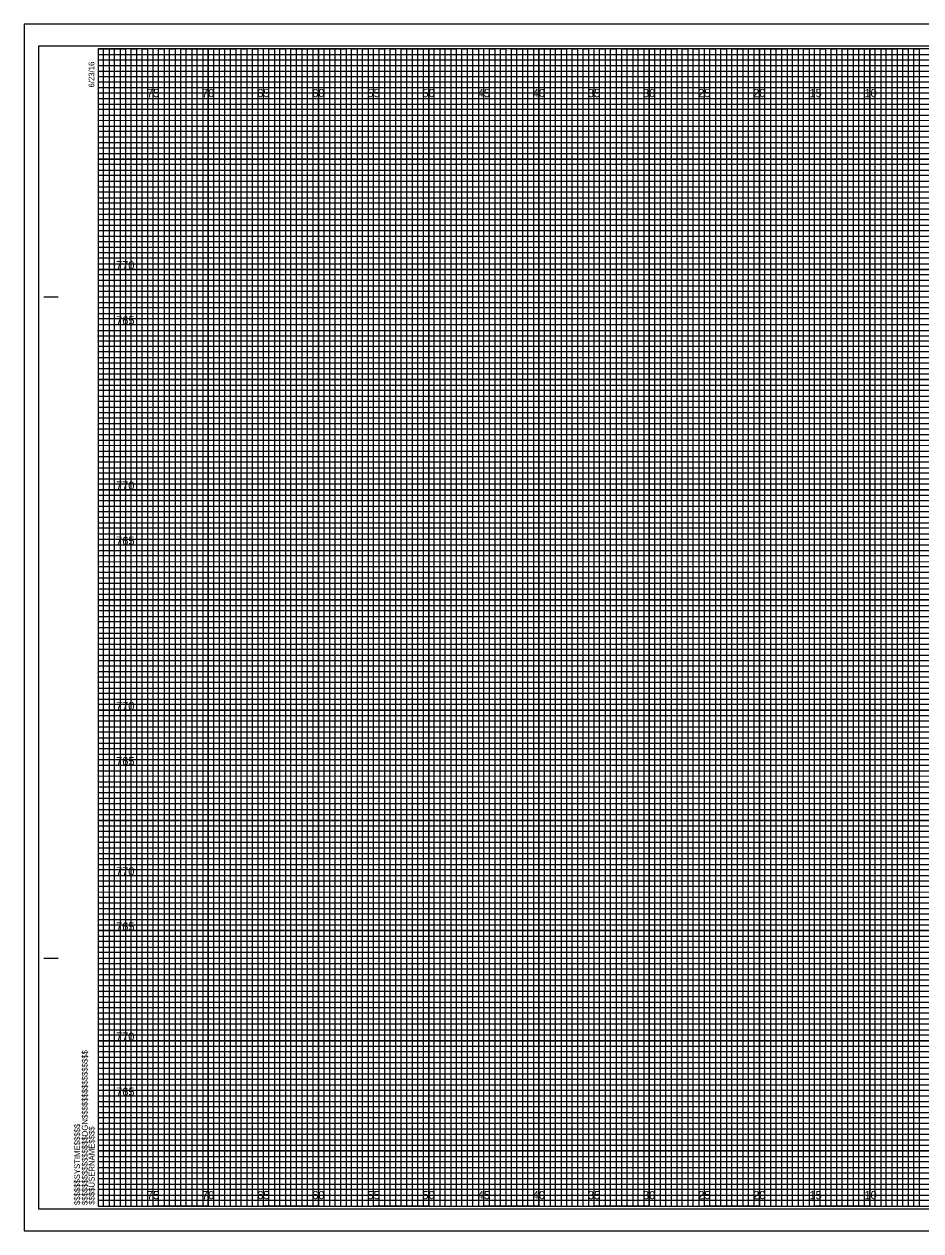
# Model space of a CAD drawing. Extents: x -7 to 162, y -2 to 107.
# Drawn here: x -6.7 to 74.6, y -2.3 to 107.3 of the extents above; entities that cross this region are included whole.
import ezdxf

# ---------------------------------------------------------------- set-up
doc = ezdxf.new("R2010")
doc.units = 0
for name, color, linetype in [('Exist XS Center Line Elevation Label', 7, 'Continuous'), ('Exist XS Ground Line', 7, 'Continuous'), ('Old_Level_63', 7, 'Continuous'), ('Prop CMT Pvmt Course 1', 7, 'Continuous'), ('Prop CMT Pvmt Course 1 CG', 7, 'Continuous'), ('Prop XS Elevation Labels', 7, 'Continuous'), ('Prop XSC Text', 7, 'Continuous'), ('Sheet Cross Section Grid Major CELL', 7, 'Continuous'), ('Sheet Cross Section Grid Minor 2 CELL', 7, 'Continuous'), ('Sheet Cutting Line CELL', 7, 'Continuous'), ('Sheet DOT Grid CELL', 7, 'Continuous')]:
    doc.layers.add(name, color=color, linetype=linetype)

msp = doc.modelspace()

# ---------------------------------------------------------------- linework, layer by layer
at = {"layer": 'Exist XS Center Line Elevation Label'}
msp.add_lwpolyline([(-5.4, -0.25), (161.2, -0.25), (161.2, 105.25), (-5.4, 105.25)], close=True, dxfattribs=at)
at = {"layer": 'Exist XS Ground Line'}
msp.add_lwpolyline([(-6.7, -2.25), (161.65, -2.25), (161.65, 107.25), (-6.7, 107.25)], close=True, dxfattribs=at)
at = {"layer": 'Old_Level_63'}
for p, q in [((-4.9, 82.5), (-3.65, 82.5)), ((-4.85, 82.5), (-3.6, 82.5)), ((-4.9, 22.5), (-3.65, 22.5)), ((-4.85, 22.5), (-3.6, 22.5)), ((0, 0), (0, 0)), ((0, 0), (0, 0)), ((0, 0), (0, 0)), ((0, 0), (0, 0)), ((0, 0), (0, 0)), ((0, 0), (0, 0)), ((0, 0), (0, 0))]:
    msp.add_line(p, q, dxfattribs=at)
msp.add_lwpolyline([(160, 105), (0, 105), (0, 0), (160, 0)], close=True, dxfattribs=at)
at = {"layer": 'Prop CMT Pvmt Course 1'}
for points in [[(0, 105), (2.5, 105), (2.5, 0), (7.5, 0), (7.5, 105), (12.5, 105), (12.5, 0), (17.5, 0), (17.5, 105), (22.5, 105), (22.5, 0), (27.5, 0), (27.5, 105), (32.5, 105), (32.5, 0), (37.5, 0), (37.5, 105), (42.5, 105), (42.5, 0), (47.5, 0), (47.5, 105), (52.5, 105), (52.5, 0), (57.5, 0), (57.5, 105), (62.5, 105), (62.5, 0), (67.5, 0), (67.5, 105), (72.5, 105), (72.5, 0), (77.5, 0)], [(0, 102.5), (137.5, 102.5)], [(0, 92.5), (160, 92.5), (160, 97.5), (0, 97.5)], [(0, 82.5), (160, 82.5), (160, 87.5), (0, 87.5)], [(0, 72.5), (160, 72.5), (160, 77.5), (0, 77.5)], [(0, 62.5), (160, 62.5), (160, 67.5), (0, 67.5)], [(0, 52.5), (160, 52.5), (160, 57.5), (0, 57.5)], [(0, 42.5), (160, 42.5), (160, 47.5), (0, 47.5)], [(0, 32.5), (160, 32.5), (160, 37.5), (0, 37.5)], [(0, 22.5), (160, 22.5), (160, 27.5), (0, 27.5)], [(0, 12.5), (160, 12.5), (160, 17.5), (0, 17.5)], [(0, 2.5), (160, 2.5), (160, 7.5), (0, 7.5)]]:
    msp.add_lwpolyline(points, dxfattribs=at)
at = {"layer": 'Prop XSC Text'}
for p, q in [((0, 104.5), (130, 104.5)), ((130, 103.99), (0, 103.99)), ((0, 103.99), (0, 103.5)), ((0, 103.5), (130, 103.5)), ((130, 102.95), (0, 102.95)), ((0, 102.95), (0, 102)), ((0, 102), (160, 102))]:
    msp.add_line(p, q, dxfattribs=at)
for points in [[(0, 101.5), (135, 101.5), (160, 101.5), (160, 101), (0, 101)], [(0, 100.5), (160, 100.5), (160, 99.5), (0, 99.5)], [(0, 99), (160, 99), (160, 98.5), (0, 98.49)], [(0, 98), (160, 98), (160, 97), (0, 97)], [(0, 96.5), (160, 96.5), (160, 96), (0, 96)], [(0, 95.5), (160, 95.5), (160, 94.5), (0, 94.5)], [(0, 94), (160, 94), (160, 93.5), (0, 93.5)], [(0, 93), (160, 93), (160, 92), (0, 92)], [(0, 91.5), (160, 91.5), (160, 91), (0, 91)], [(0, 90.5), (160, 90.5), (160, 89.5), (0, 89.5)], [(0, 89), (160, 89), (160, 88.5), (0, 88.5)], [(0, 88), (160, 88), (160, 86.98), (160, 86.5), (160, 86), (0, 86)], [(0, 87), (160, 87), (160, 86.5), (0, 86.5)], [(0, 85.5), (160, 85.5), (160, 84.5), (0, 84.52)], [(0, 84.52), (160, 84.5), (160, 84), (0, 84)], [(0, 83.5), (160, 83.5), (160, 83), (0, 83)], [(0, 82), (160, 82), (160, 81.5), (0, 81.5)], [(0, 81), (160, 81), (160, 80.5), (0, 80.5)], [(-0.04, 79.45), (160, 79.45), (160, 78.94), (-0.04, 78.94)], [(0, 78.5), (160, 78.5), (160, 78), (0, 78)], [(0, 77), (160, 77), (160, 76.5), (0, 76.5)], [(0, 76), (160, 76), (160, 75.5), (0, 75.5)], [(0, 74.5), (160, 74.5), (160, 74), (0, 74)], [(0, 73.5), (160, 73.5), (160, 73), (0, 73)], [(0, 72), (160, 72), (160, 71.5), (0, 71.5)], [(0, 71), (160, 71), (160, 70.5), (0, 70.5)], [(0, 69.5), (160, 69.5), (160, 68.99), (0, 69)], [(0, 68.5), (160, 68.5), (160, 68), (0, 68)], [(0, 67), (160, 67), (160, 66.5), (0, 66.5)], [(0, 66), (160, 66), (160, 65.5), (0, 65.5)], [(0, 64.5), (160, 64.5), (160, 64), (0, 64)], [(0, 63.5), (160, 63.5), (160, 63), (0, 63)], [(0, 62), (160, 62), (160, 61.5), (0, 61.5)], [(0, 61), (160, 61), (160, 60.5), (0, 60.5)], [(0, 59.5), (160, 59.5), (160, 59), (0, 59)], [(0, 58.5), (160.03, 58.45), (160, 58), (0, 58)], [(0, 57), (160, 57), (160, 56.5), (0, 56.5)], [(0, 56), (160, 56), (160, 55.5), (0, 55.5)], [(0, 54.5), (160, 54.5), (160, 54), (0, 54)], [(0, 53.5), (160, 53.5), (160, 53), (0, 53)], [(0, 52), (160, 52), (160, 51.5), (0, 51.5)], [(0, 51), (160, 51), (160, 50.5), (0, 50.5)], [(0, 49.5), (160, 49.5), (160, 49), (0, 49)], [(0, 48.5), (160, 48.5), (160, 48), (0, 48)], [(0, 47), (160, 47), (160, 46.5), (0, 46.5)], [(0, 46), (160, 46), (160, 45.5), (0, 45.5)], [(0, 44.5), (160, 44.5), (160, 44), (0, 44)], [(0, 43.5), (160, 43.5), (160, 43), (0, 43)], [(0, 42), (160, 42), (160, 41.5), (0, 41.5)], [(0, 41), (160, 41), (160, 40.5), (0, 40.5)], [(0, 39.5), (160, 39.5), (160, 38.99), (0, 39)], [(0, 38.5), (160, 38.5), (160, 38), (0, 38)], [(0, 37), (160, 37), (160, 36.5), (0, 36.5)], [(0, 36), (160, 36), (160, 35.5), (0, 35.5)], [(0, 34.5), (160, 34.5), (160, 34), (0, 34)], [(0, 33.5), (160, 33.5), (160, 33), (0, 33)], [(0, 32), (160, 32), (160, 31.5), (0, 31.5)], [(0, 31), (160, 31), (160, 30.5), (0, 30.5)], [(0, 29.5), (160, 29.5), (160, 29), (0, 29)], [(0, 28.5), (160.03, 28.46), (160, 28), (0, 28)], [(0, 27), (160, 27), (160, 26.5), (0, 26.5)], [(0, 26), (160, 26), (160, 25.5), (0, 25.5)], [(0, 24.5), (160, 24.5), (160, 24), (0, 24)], [(0, 23.5), (160, 23.5), (160, 23), (0, 23)], [(0, 22), (160, 22), (160, 21.5), (0, 21.5)], [(0, 21), (160, 21), (160, 20.5), (0, 20.5)], [(0, 19.5), (160, 19.5), (160, 19), (0, 19)], [(0, 18.5), (160, 18.5), (160, 18), (0, 18)], [(0, 17), (160, 17), (160, 16.5), (0, 16.5)], [(0, 16), (160, 16), (160, 15.5), (0, 15.5)], [(0, 14.5), (160, 14.5), (160, 14), (0, 14)], [(0, 13.5), (160, 13.5), (160, 13), (0, 13)], [(0, 12), (160, 12), (160, 11.5), (0, 11.5)], [(0, 11), (160, 11), (160, 10.5), (0, 10.5)], [(0, 9.5), (160, 9.5), (160, 9), (0, 9)], [(0, 8.5), (160, 8.5), (160, 8), (0, 8)], [(0, 7), (160, 7), (160, 6.5), (0, 6.5)], [(0, 6), (160, 6), (160, 5.5), (0, 5.5)], [(0, 4.5), (160, 4.5), (160, 4), (0, 4)], [(0, 3.5), (160, 3.5), (160, 3), (0, 3)], [(0, 2), (160, 2), (160, 1.5), (0, 1.5)], [(0, 1), (160, 1), (160, 0.5), (0, 0.5)]]:
    msp.add_lwpolyline(points, dxfattribs=at)
at = {"layer": 'Sheet Cross Section Grid Major CELL'}
for p, q in [((5, 105), (0, 105)), ((5, 0), (5, 105)), ((15, 105), (10, 105)), ((10, 105), (10, 0)), ((15, 0), (15, 105)), ((25, 105), (20, 105)), ((20, 105), (20, 0)), ((25, 0), (25, 105)), ((35, 105), (30, 105)), ((30, 105), (30, 0)), ((35, 0), (35, 105)), ((45, 105), (40, 105)), ((40, 105), (40, 0)), ((45, 0), (45, 105)), ((55, 105), (50, 105)), ((50, 105), (50, 0)), ((55, 0), (55, 105)), ((65, 105), (60, 105)), ((60, 105), (60, 0)), ((65, 0), (65, 105)), ((75, 105), (70, 105)), ((70, 105), (70, 0)), ((10, 0), (5, 0)), ((20, 0), (15, 0)), ((30, 0), (25, 0)), ((40, 0), (35, 0)), ((50, 0), (45, 0)), ((60, 0), (55, 0)), ((70, 0), (65, 0))]:
    msp.add_line(p, q, dxfattribs=at)
for points in [[(0, 100), (160, 100), (160, 95), (0, 95)], [(0, 90), (160, 90), (160, 85), (0, 85)], [(0, 80), (160, 80), (160, 75), (0, 75)], [(0, 70), (160, 70), (160, 65), (0, 65)], [(0, 60), (160, 60), (160, 55), (0, 55)], [(0, 50), (160, 50), (160, 45), (0, 45)], [(0, 40), (160, 40), (160, 35), (0, 35)], [(0, 30), (160, 30), (160, 25), (0, 25)], [(0, 20), (160, 20), (160, 15), (0, 15)], [(0, 10), (160, 10), (160, 5), (0, 5)]]:
    msp.add_lwpolyline(points, dxfattribs=at)
at = {"layer": 'Sheet Cross Section Grid Minor 2 CELL'}
for points in [[(0, 0), (0.5, 0), (0.5, 105), (1, 105), (1, 0)], [(1, 0), (1.5, 0), (1.5, 105), (2, 105), (2, 0)], [(2.5, 0), (3, 0), (3, 105), (3.5, 105), (3.5, 0)], [(3.5, 0), (4, 0), (4, 105), (4.5, 105), (4.5, 0)], [(5, 0), (5.5, 0), (5.5, 105), (6, 105), (6, 0)], [(6, 0), (6.5, 0), (6.5, 105), (7, 105), (7, 0)], [(7.5, 0), (8, 0), (8, 105), (8.5, 105), (8.5, 0)], [(8.5, 0), (9, 0), (9, 105), (9.5, 105), (9.5, 0)], [(10, 0), (10.5, 0), (10.5, 105), (11, 105), (11, 0)], [(11, 0), (11.5, 0), (11.5, 105), (12, 105), (12, 0)], [(12.5, 0), (13, 0), (13, 105), (13.5, 105), (13.5, 0)], [(13.5, 0), (14, 0), (14, 105), (14.5, 105), (14.5, 0)], [(15, 0), (15.5, 0), (15.5, 105), (16, 105), (16, 0)], [(16, 0), (16.5, 0), (16.5, 105), (17, 105), (17, 0)], [(17.5, 0), (18, 0), (18, 105), (18.5, 105), (18.5, 0)], [(18.5, 0), (19, 0), (19, 105), (19.5, 105), (19.5, 0)], [(20, 0), (20.5, 0), (20.5, 105), (21, 105), (21, 0)], [(21, 0), (21.5, 0), (21.5, 105), (22, 105), (22, 0)], [(22.5, 0), (23, 0), (23, 105), (23.5, 105), (23.5, 0)], [(23.5, 0), (24, 0), (24, 105), (24.5, 105), (24.5, 0)], [(25, 0), (25.5, 0), (25.5, 105), (26, 105), (26, 0)], [(26, 0), (26.5, 0), (26.5, 105), (27, 105), (27, 0)], [(27.5, 0), (28, 0), (28, 105), (28.5, 105), (28.5, 0)], [(28.5, 0), (29, 0), (29, 105), (29.5, 105), (29.5, 0)], [(30, 0), (30.5, 0), (30.5, 105), (31, 105), (31, 0)], [(31, 0), (31.5, 0), (31.5, 105), (32, 105), (32, 0)], [(32.5, 0), (33, 0), (33, 105), (33.5, 105), (33.5, 0)], [(33.5, 0), (34, 0), (34, 105), (34.5, 105), (34.5, 0)], [(35, 0), (35.5, 0), (35.5, 105), (36, 105), (36, 0)], [(36, 0), (36.5, 0), (36.5, 105), (37, 105), (37, 0)], [(37.5, 0), (38, 0), (38, 105), (38.5, 105), (38.5, 0)], [(38.5, 0), (39, 0), (39, 105), (39.5, 105), (39.5, 0)], [(40, 0), (40.5, 0), (40.5, 105), (41, 105), (41, 0)], [(41, 0), (41.5, 0), (41.5, 105), (42, 105), (42, 0)], [(42.5, 0), (43, 0), (43, 105), (43.5, 105), (43.5, 0)], [(43.5, 0), (44, 0), (44, 105), (44.5, 105), (44.5, 0)], [(45, 0), (45.5, 0), (45.5, 105), (46, 105), (46, 0)], [(46, 0), (46.5, 0), (46.5, 105), (47, 105), (47, 0)], [(47.5, 0), (48, 0), (48, 105), (48.5, 105), (48.5, 0)], [(48.5, 0), (49, 0), (49, 105), (49.5, 105), (49.5, 0)], [(50, 0), (50.5, 0), (50.5, 105), (51, 105), (51, 0)], [(51, 0), (51.5, 0), (51.5, 105), (52, 105), (52, 0)], [(52.5, 0), (53, 0), (53, 105), (53.5, 105), (53.5, 0)], [(53.5, 0), (54, 0), (54, 105), (54.5, 105), (54.5, 0)], [(55, 0), (55.5, 0), (55.5, 105), (56, 105), (56, 0)], [(56, 0), (56.5, 0), (56.5, 105), (57, 105), (57, 0)], [(57.5, 0), (58, 0), (58, 105), (58.5, 105), (58.5, 0)], [(58.5, 0), (59, 0), (59, 105), (59.5, 105), (59.5, 0)], [(60, 0), (60.5, 0), (60.5, 105), (61, 105), (61, 0)], [(61, 0), (61.5, 0), (61.5, 105), (62, 105), (62, 0)], [(62.5, 0), (63, 0), (63, 105), (63.5, 105), (63.5, 0)], [(63.5, 0), (64, 0), (64, 105), (64.5, 105), (64.5, 0)], [(65, 0), (65.5, 0), (65.5, 105), (66, 105), (66, 0)], [(66, 0), (66.5, 0), (66.5, 105), (67, 105), (67, 0)], [(67.5, 0), (68, 0), (68, 105), (68.5, 105), (68.5, 0)], [(68.5, 0), (69, 0), (69, 105), (69.5, 105), (69.5, 0)], [(70, 0), (70.5, 0), (70.5, 105), (71, 105), (71, 0)], [(71, 0), (71.5, 0), (71.5, 105), (72, 105), (72, 0)], [(72.5, 0), (73, 0), (73, 105), (73.5, 105), (73.5, 0)], [(73.5, 0), (74, 0), (74, 105), (74.5, 105), (74.5, 0)]]:
    msp.add_lwpolyline(points, dxfattribs=at)
at = {"layer": 'Sheet Cutting Line CELL'}
for p, q in [((161.65, 107.25), (-6.7, 107.25)), ((-6.7, 107.25), (-6.7, -2.25)), ((-6.7, -2.25), (161.65, -2.25))]:
    msp.add_line(p, q, dxfattribs=at)
at = {"layer": 'Sheet DOT Grid CELL'}
for p, q in [((5, 0), (5, 105)), ((10, 0), (10, 105)), ((15, 0), (15, 105)), ((20, 0), (20, 105)), ((25, 0), (25, 105)), ((30, 0), (30, 105)), ((35, 0), (35, 105)), ((40, 0), (40, 105)), ((45, 0), (45, 105)), ((50, 0), (50, 105)), ((55, 0), (55, 105)), ((60, 0), (60, 105)), ((65, 0), (65, 105)), ((70, 0), (70, 105)), ((0, 100), (160, 100)), ((0, 95), (160, 95)), ((0, 90), (160, 90)), ((0, 85), (160, 85)), ((0, 80), (160, 80)), ((0, 75), (160, 75)), ((0, 70), (160, 70)), ((0, 65), (160, 65)), ((0, 60), (160, 60)), ((0, 55), (160, 55)), ((0, 50), (160, 50)), ((0, 45), (160, 45)), ((0, 40), (160, 40)), ((0, 35), (160, 35)), ((0, 30), (160, 30)), ((0, 25), (160, 25)), ((0, 20), (160, 20)), ((0, 15), (160, 15)), ((0, 10), (160, 10)), ((0, 5), (160, 5))]:
    msp.add_line(p, q, dxfattribs=at)

# ---------------------------------------------------------------- texts
at = {"layer": 'Old_Level_63'}
for s, p in [('6/23/16', (-0.33, 101.5)), ('$$$$$$$$$$$$$$$$DGN$$$$$$$$$$$$$$$$', (-0.94, 0.09)), ('$$$$$$SYSTIME$$$$$', (-1.63, 0.09)), ('$$$$USERNAME$$$$', (-0.31, 0.12))]:
    msp.add_text(s, height=0.525, rotation=90, dxfattribs=at).set_placement(p)
at = {"layer": 'Prop CMT Pvmt Course 1 CG'}
for s, p in [('75', (4.44, 100.62)), ('70', (9.43, 100.62)), ('65', (14.44, 100.62)), ('60', (19.43, 100.62)), ('55', (24.44, 100.62)), ('50', (29.43, 100.62)), ('45', (34.44, 100.62)), ('40', (39.43, 100.62)), ('35', (44.44, 100.62)), ('30', (49.43, 100.62)), ('25', (54.44, 100.62)), ('20', (59.43, 100.62)), ('15', (64.53, 100.62)), ('10', (69.52, 100.62)), ('75', (4.44, 0.62)), ('70', (9.43, 0.62)), ('65', (14.44, 0.62)), ('60', (19.43, 0.62)), ('55', (24.44, 0.62)), ('50', (29.43, 0.62)), ('45', (34.44, 0.62)), ('40', (39.43, 0.62)), ('35', (44.44, 0.62)), ('30', (49.43, 0.62)), ('25', (54.44, 0.62)), ('20', (59.43, 0.62)), ('15', (64.53, 0.62)), ('10', (69.52, 0.62))]:
    msp.add_text(s, height=0.75, dxfattribs=at).set_placement(p)
at = {"layer": 'Prop XS Elevation Labels'}
for s, p in [('770', (1.63, 85)), ('765', (1.64, 80)), ('770', (1.63, 65)), ('765', (1.64, 60)), ('770', (1.63, 45)), ('765', (1.64, 40)), ('770', (1.63, 30)), ('765', (1.64, 25)), ('770', (1.63, 15)), ('765', (1.64, 10))]:
    msp.add_text(s, height=0.75, dxfattribs=at).set_placement(p)

doc.saveas('drawing.dxf')
